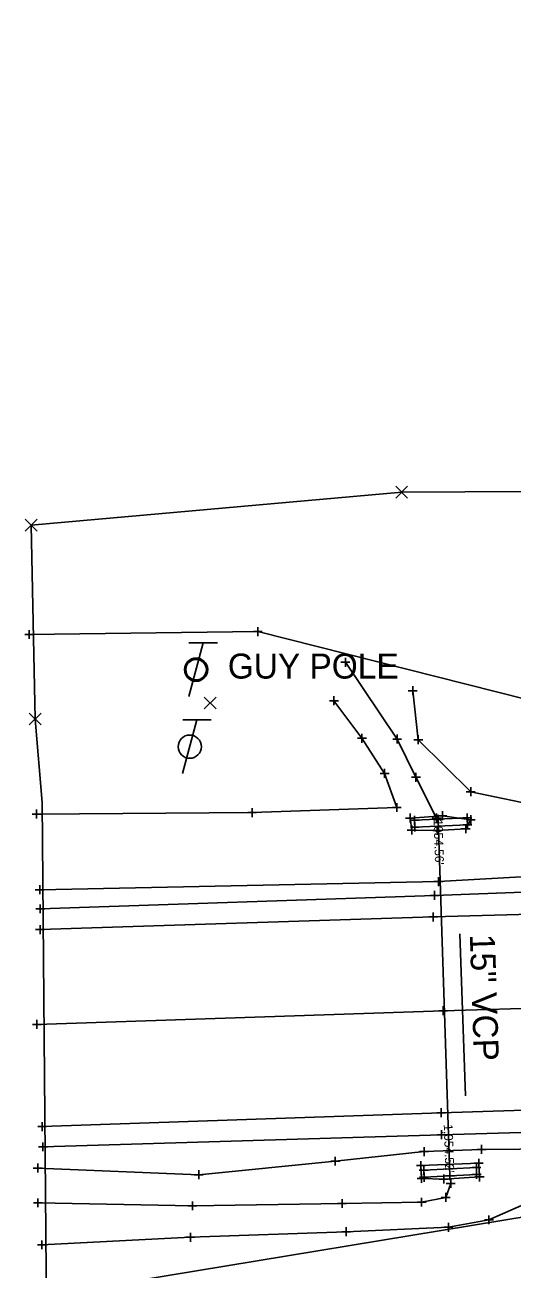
# Model space of a CAD drawing. Extents: x 211013 to 211654, y 505587 to 505872.
# Drawn here: x 211013.2 to 211067.8, y 505686.3 to 505825.7 of the extents above; entities that cross this region are included whole.
import ezdxf

# ---------------------------------------------------------------- set-up
doc = ezdxf.new("R2010")
doc.units = 0
for name, color, linetype in [('_CIVIL_CONSTRUCTION', 7, 'Continuous'), ('BR_P_Gen_Porous_Backfill', 7, 'Continuous'), ('CL_X_RW', 7, 'Continuous'), ('DR_X_Storm_Sewer', 7, 'Continuous'), ('DR_X_Text', 7, 'Continuous'), ('DV_X_Section_VMS_Line', 7, 'Continuous'), ('GE_X_Alignment', 7, 'Continuous'), ('GE_X_Alignment_1000_Curve_Data', 7, 'Continuous'), ('GE_X_Alignment_100_Curve_Data', 7, 'Continuous'), ('GE_X_Alignment_100_Stations', 7, 'Continuous'), ('GE_X_Alignment_500_Curve_Data', 7, 'Continuous'), ('GE_X_Alignment_500_Stations', 7, 'Continuous'), ('PM_X_CL_Dashed', 7, 'Continuous'), ('PM_X_Edge_Line', 7, 'Continuous'), ('RW_X_Esmt_SH', 7, 'Continuous'), ('SC_Scratch1', 7, 'Continuous'), ('SV_P_Control_Cells_Set', 7, 'Continuous'), ('SV_X_Terrain_Boundary', 7, 'Continuous'), ('SV_X_Text', 7, 'Continuous')]:
    doc.layers.add(name, color=color, linetype=linetype)

msp = doc.modelspace()

# ---------------------------------------------------------------- linework, layer by layer
at = {"layer": '_CIVIL_CONSTRUCTION'}
for points in [[(211056.6, 505735.53), (211056.41, 505736.87), (211060.03, 505737.14), (211063.22, 505736.68), (211062.64, 505735.67), (211059.45, 505735.49)], [(211057.62, 505697.94), (211057.7, 505696.5), (211060.18, 505696.43), (211064.2, 505696.66), (211064.1, 505698.19)]]:
    msp.add_lwpolyline(points, close=True, dxfattribs=at)
at = {"layer": 'BR_P_Gen_Porous_Backfill'}
msp.add_lwpolyline([(211014.6, 505713.75), (211060.12, 505715.29), (211110.48, 505716.76), (211159.6, 505717.98), (211200.36, 505719.77), (211209.6, 505719.61), (211259.6, 505721.26), (211285.44, 505722.36), (211310.01, 505723.01), (211334.64, 505723.96), (211359.49, 505724.7), (211409.16, 505726.49), (211459.68, 505727.94), (211509.31, 505729.66), (211559.47, 505731.15), (211610.5, 505732.77), (211648.15, 505734.06)], dxfattribs=at)
at = {"layer": 'CL_X_RW'}
for p, q in [((211034.83, 505756.5), (211031.63, 505756.5)), ((211033.23, 505756.5), (211031.63, 505750.5)), ((211032.53, 505747.87), (211030.92, 505741.87)), ((211034.13, 505747.87), (211030.93, 505747.87))]:
    msp.add_line(p, q, dxfattribs=at)
for centre, radius in [((211032.43, 505753.5), 1.3), ((211032.43, 505753.5), 1.15), ((211031.72, 505744.87), 1.3)]:
    msp.add_circle(centre, radius, dxfattribs=at)
at = {"layer": 'DR_X_Storm_Sewer'}
msp.add_line((211059.54, 505736.73), (211060.88, 505696.8), dxfattribs=at)
at = {"layer": 'DR_X_Text'}
msp.add_line((211062.6, 505705.76), (211062, 505723.92), dxfattribs=at)
at = {"layer": 'DV_X_Section_VMS_Line'}
for p, q in [((211013.74, 505757.94), (211013.74, 505756.94)), ((211038.85, 505757.76), (211039.85, 505757.76)), ((211039.35, 505758.26), (211039.35, 505757.26)), ((211039.35, 505757.76), (211039.35, 505757.76)), ((211013.24, 505757.44), (211014.24, 505757.44)), ((211013.74, 505757.44), (211013.74, 505757.44)), ((211049.16, 505754.83), (211049.16, 505753.83)), ((211048.66, 505754.33), (211049.66, 505754.33)), ((211049.16, 505754.33), (211049.16, 505754.33)), ((211056.21, 505751.14), (211057.21, 505751.14)), ((211056.71, 505751.64), (211056.71, 505750.64)), ((211056.71, 505751.14), (211056.71, 505751.14)), ((211047.37, 505750.02), (211048.37, 505750.02)), ((211047.87, 505750.52), (211047.87, 505749.52)), ((211047.87, 505750.02), (211047.87, 505750.02)), ((211050.52, 505745.82), (211051.52, 505745.82)), ((211051.02, 505746.32), (211051.02, 505745.32)), ((211051.02, 505745.82), (211051.02, 505745.82)), ((211054.46, 505745.72), (211055.46, 505745.72)), ((211054.96, 505746.22), (211054.96, 505745.22)), ((211054.96, 505745.72), (211054.96, 505745.72)), ((211056.83, 505745.65), (211057.83, 505745.65)), ((211057.33, 505746.15), (211057.33, 505745.15)), ((211057.33, 505745.65), (211057.33, 505745.65)), ((211053.55, 505742.38), (211053.55, 505741.38)), ((211053.05, 505741.88), (211054.05, 505741.88)), ((211053.55, 505741.88), (211053.55, 505741.88)), ((211056.57, 505741.45), (211057.57, 505741.45)), ((211057.07, 505741.95), (211057.07, 505740.95)), ((211057.07, 505741.45), (211057.07, 505741.45)), ((211062.7, 505739.83), (211063.7, 505739.83)), ((211063.2, 505740.33), (211063.2, 505739.33)), ((211063.2, 505739.83), (211063.2, 505739.83)), ((211054.92, 505738.56), (211054.92, 505737.56)), ((211014.05, 505737.32), (211015.05, 505737.32)), ((211014.55, 505737.82), (211014.55, 505736.82)), ((211014.55, 505737.32), (211014.55, 505737.32)), ((211038.21, 505737.48), (211039.21, 505737.48)), ((211038.71, 505737.98), (211038.71, 505736.98)), ((211038.71, 505737.48), (211038.71, 505737.48)), ((211054.42, 505738.06), (211055.42, 505738.06)), ((211054.92, 505738.06), (211054.92, 505738.06)), ((211055.91, 505736.87), (211056.91, 505736.87)), ((211056.41, 505737.37), (211056.41, 505736.37)), ((211056.41, 505736.87), (211056.41, 505736.87)), ((211056.91, 505737.12), (211056.91, 505736.12)), ((211058.88, 505736.88), (211059.88, 505736.88)), ((211059.38, 505737.38), (211059.38, 505736.38)), ((211059.38, 505736.88), (211059.38, 505736.88)), ((211059.53, 505737.14), (211060.53, 505737.14)), ((211060.03, 505737.64), (211060.03, 505736.64)), ((211060.03, 505737.14), (211060.03, 505737.14)), ((211062.31, 505736.9), (211063.31, 505736.9)), ((211062.81, 505737.4), (211062.81, 505736.4)), ((211062.81, 505736.9), (211062.81, 505736.9)), ((211063.22, 505737.18), (211063.22, 505736.18)), ((211056.1, 505735.53), (211057.1, 505735.53)), ((211056.41, 505736.62), (211057.41, 505736.62)), ((211056.44, 505735.86), (211057.44, 505735.86)), ((211056.6, 505736.03), (211056.6, 505735.03)), ((211056.6, 505735.53), (211056.6, 505735.53)), ((211056.91, 505736.62), (211056.91, 505736.62)), ((211056.94, 505736.36), (211056.94, 505735.36)), ((211056.94, 505735.86), (211056.94, 505735.86)), ((211058.95, 505735.49), (211059.95, 505735.49)), ((211059.45, 505735.99), (211059.45, 505734.99)), ((211059.45, 505735.49), (211059.45, 505735.49)), ((211062.14, 505735.67), (211063.14, 505735.67)), ((211062.34, 505736.13), (211063.34, 505736.13)), ((211062.64, 505736.17), (211062.64, 505735.17)), ((211062.64, 505735.67), (211062.64, 505735.67)), ((211062.72, 505736.68), (211063.72, 505736.68)), ((211062.84, 505736.63), (211062.84, 505735.63)), ((211062.84, 505736.13), (211062.84, 505736.13)), ((211063.22, 505736.68), (211063.22, 505736.68)), ((211059.08, 505729.76), (211060.08, 505729.76)), ((211059.58, 505730.26), (211059.58, 505729.26)), ((211059.58, 505729.76), (211059.58, 505729.76)), ((211014.4, 505728.85), (211015.4, 505728.85)), ((211014.9, 505729.35), (211014.9, 505728.35)), ((211014.9, 505728.85), (211014.9, 505728.85)), ((211059.16, 505728.71), (211059.16, 505727.71)), ((211014.96, 505727.2), (211014.96, 505726.2)), ((211058.66, 505728.21), (211059.66, 505728.21)), ((211059.16, 505728.21), (211059.16, 505728.21)), ((211014.46, 505726.7), (211015.46, 505726.7)), ((211014.96, 505726.7), (211014.96, 505726.7)), ((211058.5, 505725.8), (211059.5, 505725.8)), ((211058.5, 505725.8), (211059.5, 505725.8)), ((211059, 505726.3), (211059, 505725.3)), ((211059, 505726.3), (211059, 505725.3)), ((211059, 505725.8), (211059, 505725.8)), ((211059, 505725.8), (211059, 505725.8)), ((211014.44, 505724.38), (211015.44, 505724.38)), ((211014.44, 505724.38), (211015.44, 505724.38)), ((211014.94, 505724.88), (211014.94, 505723.88)), ((211014.94, 505724.88), (211014.94, 505723.88)), ((211014.94, 505724.38), (211014.94, 505724.38)), ((211014.94, 505724.38), (211014.94, 505724.38)), ((211059.62, 505715.29), (211060.62, 505715.29)), ((211059.62, 505715.29), (211060.62, 505715.29)), ((211060.12, 505715.79), (211060.12, 505714.79)), ((211060.12, 505715.79), (211060.12, 505714.79)), ((211060.12, 505715.29), (211060.12, 505715.29)), ((211060.12, 505715.29), (211060.12, 505715.29)), ((211014.1, 505713.75), (211015.1, 505713.75)), ((211014.1, 505713.75), (211015.1, 505713.75)), ((211014.6, 505714.25), (211014.6, 505713.25)), ((211014.6, 505714.25), (211014.6, 505713.25)), ((211014.6, 505713.75), (211014.6, 505713.75)), ((211014.6, 505713.75), (211014.6, 505713.75)), ((211059.39, 505703.86), (211060.39, 505703.86)), ((211059.39, 505703.86), (211060.39, 505703.86)), ((211059.89, 505704.36), (211059.89, 505703.36)), ((211059.89, 505704.36), (211059.89, 505703.36)), ((211059.89, 505703.86), (211059.89, 505703.86)), ((211059.89, 505703.86), (211059.89, 505703.86)), ((211014.68, 505702.3), (211015.68, 505702.3)), ((211014.68, 505702.3), (211015.68, 505702.3)), ((211015.18, 505702.8), (211015.18, 505701.8)), ((211015.18, 505702.8), (211015.18, 505701.8)), ((211015.18, 505702.3), (211015.18, 505702.3)), ((211015.18, 505702.3), (211015.18, 505702.3)), ((211059.93, 505701.9), (211059.93, 505700.9)), ((211015.26, 505700.54), (211015.26, 505699.54)), ((211059.43, 505701.4), (211060.43, 505701.4)), ((211059.93, 505701.4), (211059.93, 505701.4)), ((211014.76, 505700.04), (211015.76, 505700.04)), ((211015.26, 505700.04), (211015.26, 505700.04)), ((211057.48, 505699.51), (211058.48, 505699.51)), ((211057.98, 505700.01), (211057.98, 505699.01)), ((211057.98, 505699.51), (211057.98, 505699.51)), ((211063.92, 505699.75), (211064.92, 505699.75)), ((211064.42, 505700.25), (211064.42, 505699.25)), ((211064.42, 505699.75), (211064.42, 505699.75)), ((211014.68, 505698.16), (211014.68, 505697.16)), ((211047.52, 505698.43), (211048.52, 505698.43)), ((211048.02, 505698.93), (211048.02, 505697.93)), ((211048.02, 505698.43), (211048.02, 505698.43)), ((211057.12, 505697.94), (211058.12, 505697.94)), ((211057.62, 505698.44), (211057.62, 505697.44)), ((211057.62, 505697.94), (211057.62, 505697.94)), ((211057.94, 505697.91), (211057.94, 505696.91)), ((211063.35, 505697.72), (211064.35, 505697.72)), ((211063.6, 505698.19), (211064.6, 505698.19)), ((211063.85, 505698.22), (211063.85, 505697.22)), ((211063.85, 505697.72), (211063.85, 505697.72)), ((211064.1, 505698.69), (211064.1, 505697.69)), ((211064.1, 505698.19), (211064.1, 505698.19)), ((211014.18, 505697.66), (211015.18, 505697.66)), ((211014.68, 505697.66), (211014.68, 505697.66)), ((211032.22, 505696.91), (211033.22, 505696.91)), ((211032.72, 505697.41), (211032.72, 505696.41)), ((211032.72, 505696.91), (211032.72, 505696.91)), ((211057.2, 505696.5), (211058.2, 505696.5)), ((211057.44, 505697.41), (211058.44, 505697.41)), ((211057.48, 505696.63), (211058.48, 505696.63)), ((211057.7, 505697), (211057.7, 505696)), ((211057.7, 505696.5), (211057.7, 505696.5)), ((211057.94, 505697.41), (211057.94, 505697.41)), ((211057.98, 505697.13), (211057.98, 505696.13)), ((211057.98, 505696.63), (211057.98, 505696.63)), ((211059.68, 505696.43), (211060.68, 505696.43)), ((211060.18, 505696.93), (211060.18, 505695.93)), ((211060.18, 505696.43), (211060.18, 505696.43)), ((211060.96, 505696.44), (211060.96, 505695.44)), ((211063.36, 505696.94), (211064.36, 505696.94)), ((211063.7, 505696.66), (211064.7, 505696.66)), ((211063.86, 505697.44), (211063.86, 505696.44)), ((211063.86, 505696.94), (211063.86, 505696.94)), ((211064.2, 505697.16), (211064.2, 505696.16)), ((211064.2, 505696.66), (211064.2, 505696.66)), ((211060.46, 505695.94), (211061.46, 505695.94)), ((211060.96, 505695.94), (211060.96, 505695.94)), ((211014.21, 505693.76), (211015.21, 505693.76)), ((211014.71, 505694.26), (211014.71, 505693.26)), ((211014.71, 505693.76), (211014.71, 505693.76)), ((211032.03, 505693.93), (211032.03, 505692.93)), ((211048.29, 505693.69), (211049.29, 505693.69)), ((211048.79, 505694.19), (211048.79, 505693.19)), ((211048.79, 505693.69), (211048.79, 505693.69)), ((211057.2, 505693.84), (211058.2, 505693.84)), ((211057.7, 505694.34), (211057.7, 505693.34)), ((211057.7, 505693.84), (211057.7, 505693.84)), ((211059.9, 505694.37), (211060.9, 505694.37)), ((211060.4, 505694.87), (211060.4, 505693.87)), ((211060.4, 505694.37), (211060.4, 505694.37)), ((211031.53, 505693.43), (211032.53, 505693.43)), ((211032.03, 505693.43), (211032.03, 505693.43)), ((211065.25, 505692.36), (211065.25, 505691.36)), ((211049.25, 505691.02), (211049.25, 505690.02)), ((211060.21, 505691.02), (211061.21, 505691.02)), ((211060.71, 505691.52), (211060.71, 505690.52)), ((211060.71, 505691.02), (211060.71, 505691.02)), ((211064.75, 505691.86), (211065.75, 505691.86)), ((211065.25, 505691.86), (211065.25, 505691.86)), ((211015.14, 505689.56), (211015.14, 505688.56)), ((211031.29, 505689.9), (211032.29, 505689.9)), ((211031.79, 505690.4), (211031.79, 505689.4)), ((211031.79, 505689.9), (211031.79, 505689.9)), ((211048.75, 505690.52), (211049.75, 505690.52)), ((211049.25, 505690.52), (211049.25, 505690.52)), ((211014.64, 505689.06), (211015.64, 505689.06)), ((211015.14, 505689.06), (211015.14, 505689.06))]:
    msp.add_line(p, q, dxfattribs=at)
at = {"layer": 'GE_X_Alignment'}
for points in [[(211013.74, 505757.44), (211039.35, 505757.76), (211089.44, 505745.11), (211110.4, 505747.3), (211138.84, 505748.86), (211159.65, 505748.75), (211188.99, 505747.67), (211209.12, 505746.31), (211240.23, 505750.06), (211264.84, 505765.09), (211274.1, 505775.82), (211283.53, 505792.47), (211291.8, 505810.61), (211301.47, 505825.74)], [(211015.26, 505683.32), (211080.5, 505694.08), (211109.4, 505697.19), (211135.16, 505699.18), (211157.57, 505696.9), (211176.08, 505692.43), (211181.06, 505676.6), (211185.07, 505653.12), (211186.49, 505625.48), (211186.51, 505603.87)]]:
    msp.add_lwpolyline(points, dxfattribs=at)
at = {"layer": 'GE_X_Alignment_1000_Curve_Data'}
for points in [[(211049.16, 505754.33), (211054.96, 505745.72), (211057.07, 505741.45), (211059.38, 505736.88)], [(211014.71, 505693.76), (211032.03, 505693.43), (211048.79, 505693.69), (211057.7, 505693.84), (211060.4, 505694.37), (211060.96, 505695.94)]]:
    msp.add_lwpolyline(points, dxfattribs=at)
at = {"layer": 'GE_X_Alignment_100_Curve_Data'}
msp.add_lwpolyline([(211014.9, 505728.85), (211059.58, 505729.76), (211084.8, 505731.17), (211109.64, 505731.61), (211140.67, 505733.25), (211159.39, 505734.06), (211188.38, 505734.44), (211208.87, 505734.5), (211237.94, 505735.61)], dxfattribs=at)
at = {"layer": 'GE_X_Alignment_100_Stations'}
for points in [[(211056.71, 505751.14), (211057.33, 505745.65), (211063.2, 505739.83), (211071.49, 505738.1), (211085.28, 505737.62), (211109.68, 505739.14), (211139.54, 505738.66), (211159.15, 505740.9), (211189.44, 505740.71), (211208.93, 505741.64), (211236.13, 505744.19)], [(211014.55, 505737.32), (211038.71, 505737.48), (211054.92, 505738.06), (211053.55, 505741.88), (211051.02, 505745.82), (211047.87, 505750.02)], [(211014.68, 505697.66), (211032.72, 505696.91), (211048.02, 505698.43), (211057.98, 505699.51), (211064.42, 505699.75), (211081.55, 505699.9), (211110.96, 505700.67), (211135.26, 505701.72), (211160.19, 505702.83)], [(211015.14, 505689.06), (211031.79, 505689.9), (211049.25, 505690.52), (211060.71, 505691.02), (211065.25, 505691.86), (211069.83, 505693.86), (211080.5, 505694.08), (211099.86, 505694.34), (211109.4, 505697.19), (211135.16, 505699.18), (211160.37, 505699.36)]]:
    msp.add_lwpolyline(points, dxfattribs=at)
at = {"layer": 'GE_X_Alignment_500_Curve_Data'}
for points in [[(211014.94, 505724.38), (211059, 505725.8), (211109.78, 505727.2), (211159.51, 505728.76), (211208.82, 505730.58), (211259.8, 505732.07), (211285.15, 505733.09), (211309.66, 505733.86), (211334.86, 505734.83), (211359.19, 505735.69), (211410.23, 505737.38), (211459.71, 505738.84), (211509.76, 505740.37), (211559.97, 505741.95), (211609.77, 505743.95), (211648.34, 505745.17)], [(211015.18, 505702.3), (211059.89, 505703.86), (211110.08, 505705.46), (211159.91, 505707.21), (211210, 505708.77), (211260.13, 505710.64), (211285.52, 505711.3), (211310.08, 505712.21), (211335.57, 505712.89), (211359.35, 505713.87), (211409.23, 505715.38), (211460.17, 505716.91), (211509.67, 505718.76), (211560, 505720.31), (211609.44, 505722.11), (211648.41, 505723.36)]]:
    msp.add_lwpolyline(points, dxfattribs=at)
at = {"layer": 'GE_X_Alignment_500_Stations'}
for points in [[(211014.96, 505726.7), (211059.16, 505728.21), (211109.79, 505730.12), (211159.49, 505731.89), (211208.81, 505733.15), (211259.88, 505734.99), (211284.98, 505735.99), (211309.59, 505736.29), (211335.02, 505737.47), (211359.19, 505738.25), (211410.26, 505740.04), (211459.78, 505741.71), (211509.56, 505743.25), (211560.07, 505744.76), (211609.93, 505746.61), (211648.16, 505748.08)], [(211015.26, 505700.04), (211059.93, 505701.4), (211110.76, 505702.87), (211160.11, 505704.52), (211209.98, 505706.26), (211260.3, 505708.4), (211285.53, 505709.32), (211310.23, 505709.72), (211335.79, 505710.84), (211359.8, 505710.9), (211409.56, 505712.88), (211460.5, 505714.51), (211509.53, 505715.91), (211559.92, 505717.47), (211609.34, 505719.66), (211648.64, 505720.82)]]:
    msp.add_lwpolyline(points, dxfattribs=at)
at = {"layer": 'PM_X_CL_Dashed'}
msp.add_lwpolyline([(211014.6, 505713.75), (211060.12, 505715.29), (211110.48, 505716.76), (211159.6, 505717.98), (211200.36, 505719.77)], dxfattribs=at)
at = {"layer": 'PM_X_Edge_Line'}
for points in [[(211014.94, 505724.38), (211059, 505725.8), (211109.78, 505727.2), (211159.51, 505728.76), (211208.82, 505730.58), (211259.8, 505732.07), (211285.15, 505733.09), (211309.66, 505733.86), (211334.86, 505734.83), (211359.19, 505735.69), (211410.23, 505737.38), (211459.71, 505738.84), (211509.76, 505740.37), (211559.97, 505741.95), (211609.77, 505743.95), (211648.34, 505745.17)], [(211015.18, 505702.3), (211059.89, 505703.86), (211110.08, 505705.46), (211159.91, 505707.21), (211210, 505708.77), (211260.13, 505710.64), (211285.52, 505711.3), (211310.08, 505712.21), (211335.57, 505712.89), (211359.35, 505713.87), (211409.23, 505715.38), (211460.17, 505716.91), (211509.67, 505718.76), (211560, 505720.31), (211609.44, 505722.11), (211648.41, 505723.36)]]:
    msp.add_lwpolyline(points, dxfattribs=at)
at = {"layer": 'RW_X_Esmt_SH'}
for p, q in [((211054.8, 505772.73), (211056.13, 505774.07)), ((211054.8, 505774.07), (211056.13, 505772.73)), ((211013.29, 505769.03), (211014.62, 505770.37)), ((211013.29, 505770.37), (211014.62, 505769.03)), ((211033.33, 505749.1), (211034.66, 505750.43)), ((211033.33, 505750.43), (211034.66, 505749.1)), ((211013.71, 505747.3), (211015.05, 505748.64)), ((211013.71, 505748.64), (211015.05, 505747.3))]:
    msp.add_line(p, q, dxfattribs=at)
at = {"layer": 'SC_Scratch1'}
for p, q in [((211059.04, 505736.73), (211060.04, 505736.73)), ((211059.54, 505737.23), (211059.54, 505736.23)), ((211059.54, 505736.73), (211059.54, 505736.73)), ((211060.38, 505696.8), (211061.38, 505696.8)), ((211060.88, 505697.3), (211060.88, 505696.3)), ((211060.88, 505696.8), (211060.88, 505696.8))]:
    msp.add_line(p, q, dxfattribs=at)
at = {"layer": 'SV_P_Control_Cells_Set'}
for points in [[(211062.81, 505736.9), (211062.84, 505736.13), (211056.94, 505735.86), (211056.91, 505736.62)], [(211063.86, 505696.94), (211063.85, 505697.72), (211057.94, 505697.41), (211057.98, 505696.63)]]:
    msp.add_lwpolyline(points, close=True, dxfattribs=at)
at = {"layer": 'SV_X_Terrain_Boundary'}
msp.add_lwpolyline([(211258.57, 505812.76), (211238.01, 505789.67), (211208.95, 505771.3), (211161.33, 505774.75), (211112.02, 505773.7), (211055.47, 505773.4), (211013.95, 505769.7), (211014.38, 505747.97), (211015.17, 505738.62), (211015.65, 505681.68), (211013.46, 505661.46), (211064.36, 505661.96), (211109.35, 505661.26), (211151.86, 505632.96), (211149.18, 505606.08), (211186.51, 505603.87), (211206.35, 505610.45), (211218.51, 505613.39), (211247.2, 505610.15), (211268.66, 505610.6)], dxfattribs=at)

# ---------------------------------------------------------------- texts
at = {"layer": 'DR_X_Text'}
msp.add_text('15" VCP', height=2.8, rotation=271.9139, dxfattribs=at).set_placement((211063.1, 505723.84))
at = {"layer": 'SC_Scratch1'}
for s, p in [("1054.56'", (211059.04, 505736.72)), ("1,054.52'", (211060.18, 505702.56))]:
    msp.add_text(s, height=1, rotation=271.9139, dxfattribs=at).set_placement(p)
at = {"layer": 'SV_X_Text'}
msp.add_text('GUY POLE', height=2.8, dxfattribs=at).set_placement((211035.98, 505752.5))

doc.saveas('drawing.dxf')
